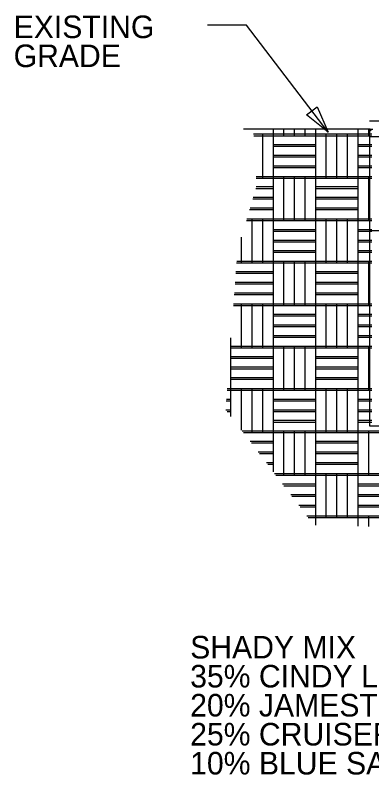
# Model space of a CAD drawing. Extents: x 9915.7 to 9955.7, y 9888.6 to 9936.3.
# Drawn here: x 9915.74 to 9926.81, y 9912.72 to 9936.27 of the extents above; entities that cross this region are included whole.
import ezdxf

# ---------------------------------------------------------------- set-up
doc = ezdxf.new("R2010")
doc.units = 0
for name, color, linetype in [('Default', 7, 'Continuous'), ('G-ANNO-TEXT', 7, 'Continuous'), ('G-ANNO-TTXT', 7, 'Continuous'), ('G-DETL-LINE', 7, 'Continuous'), ('G-DETL-PATT', 7, 'Continuous'), ('L-PLNT-SEED', 7, 'Continuous')]:
    doc.layers.add(name, color=color, linetype=linetype)

# ---------------------------------------------------------------- blocks, each defined once
blk = doc.blocks.new('TERARR')
at = {"layer": 'Default'}
blk.add_lwpolyline([(-0.667, 0.167), (0, 0), (-0.667, -0.167)], close=True, dxfattribs=at)

msp = doc.modelspace()

# ---------------------------------------------------------------- linework, layer by layer
at = {"layer": 'Default'}
for p, q in [((9926.715, 9932.587), (9926.715, 9932.714)), ((9926.715, 9932.534), (9926.715, 9932.714)), ((9926.737, 9932.731), (9926.843, 9932.731)), ((9926.715, 9929.956), (9926.715, 9931.271)), ((9926.715, 9929.903), (9926.715, 9931.219))]:
    msp.add_line(p, q, dxfattribs=at)
at = {"layer": 'G-ANNO-TEXT'}
msp.add_lwpolyline([(9925.458, 9932.644), (9922.921, 9935.959), (9921.709, 9935.959)], dxfattribs=at)
at = {"layer": 'G-ANNO-TTXT'}
msp.add_line((9926.737, 9932.993), (9943.294, 9932.993), dxfattribs=at)
at = {"layer": 'G-DETL-LINE'}
for p, q in [((9926.76, 9932.731), (9922.831, 9932.731)), ((9926.737, 9932.731), (9926.737, 9923.539)), ((9926.737, 9932.508), (9943.291, 9932.508)), ((9926.737, 9929.597), (9943.23, 9929.597)), ((9926.737, 9923.539), (9942.996, 9923.539))]:
    msp.add_line(p, q, dxfattribs=at)
at = {"layer": 'G-DETL-PATT'}
for p, q in [((9923.755, 9932.587), (9923.755, 9932.714)), ((9923.755, 9932.534), (9923.755, 9932.714)), ((9924.084, 9932.587), (9924.084, 9932.714)), ((9924.084, 9932.534), (9924.084, 9932.714)), ((9924.413, 9932.587), (9924.413, 9932.714)), ((9924.413, 9932.534), (9924.413, 9932.714)), ((9924.742, 9932.587), (9924.742, 9932.714)), ((9924.742, 9932.534), (9924.742, 9932.714)), ((9925.071, 9932.587), (9925.071, 9932.714)), ((9925.071, 9932.534), (9925.071, 9932.714)), ((9926.386, 9932.587), (9926.386, 9932.714)), ((9926.386, 9932.534), (9926.386, 9932.714)), ((9923.143, 9932.587), (9926.813, 9932.587)), ((9923.153, 9932.534), (9926.813, 9932.534)), ((9923.426, 9931.271), (9923.426, 9932.587)), ((9923.426, 9931.219), (9923.426, 9932.534)), ((9923.755, 9931.271), (9923.755, 9932.587)), ((9923.755, 9932.587), (9925.071, 9932.587)), ((9923.755, 9931.219), (9923.755, 9932.534)), ((9923.755, 9932.534), (9925.071, 9932.534)), ((9925.071, 9931.271), (9925.071, 9932.587)), ((9925.071, 9931.219), (9925.071, 9932.534)), ((9925.399, 9931.271), (9925.399, 9932.587)), ((9925.399, 9931.219), (9925.399, 9932.534)), ((9925.728, 9931.271), (9925.728, 9932.587)), ((9925.728, 9931.219), (9925.728, 9932.534)), ((9926.057, 9931.271), (9926.057, 9932.587)), ((9926.057, 9931.219), (9926.057, 9932.534)), ((9926.386, 9931.271), (9926.386, 9932.587)), ((9926.386, 9932.587), (9926.813, 9932.587)), ((9926.386, 9931.219), (9926.386, 9932.534)), ((9926.386, 9932.534), (9926.813, 9932.534)), ((9923.755, 9932.258), (9925.071, 9932.258)), ((9926.386, 9932.258), (9926.813, 9932.258)), ((9923.755, 9932.205), (9925.071, 9932.205)), ((9926.386, 9932.205), (9926.813, 9932.205)), ((9923.755, 9931.929), (9925.071, 9931.929)), ((9923.755, 9931.876), (9925.071, 9931.876)), ((9926.386, 9931.929), (9926.813, 9931.929)), ((9926.386, 9931.876), (9926.813, 9931.876)), ((9923.755, 9931.6), (9925.071, 9931.6)), ((9923.755, 9931.548), (9925.071, 9931.548)), ((9926.386, 9931.6), (9926.813, 9931.6)), ((9926.386, 9931.548), (9926.813, 9931.548)), ((9923.223, 9931.271), (9926.813, 9931.271)), ((9923.755, 9929.956), (9923.755, 9931.271)), ((9924.084, 9929.956), (9924.084, 9931.271)), ((9924.413, 9929.956), (9924.413, 9931.271)), ((9924.742, 9929.956), (9924.742, 9931.271)), ((9925.071, 9929.956), (9925.071, 9931.271)), ((9926.386, 9929.956), (9926.386, 9931.271)), ((9923.223, 9931.219), (9926.813, 9931.219)), ((9923.755, 9929.903), (9923.755, 9931.219)), ((9924.084, 9929.903), (9924.084, 9931.219)), ((9924.413, 9929.903), (9924.413, 9931.219)), ((9924.742, 9929.903), (9924.742, 9931.219)), ((9925.071, 9929.903), (9925.071, 9931.219)), ((9926.386, 9929.903), (9926.386, 9931.219)), ((9923.755, 9930.89), (9923.215, 9930.89)), ((9923.755, 9930.943), (9923.223, 9930.943)), ((9926.386, 9930.943), (9925.071, 9930.943)), ((9926.386, 9930.89), (9925.071, 9930.89)), ((9923.755, 9930.561), (9923.117, 9930.561)), ((9923.755, 9930.614), (9923.133, 9930.614)), ((9926.386, 9930.614), (9925.071, 9930.614)), ((9926.386, 9930.561), (9925.071, 9930.561)), ((9923.755, 9930.232), (9923.019, 9930.232)), ((9923.755, 9930.285), (9923.035, 9930.285)), ((9926.386, 9930.285), (9925.071, 9930.285)), ((9926.386, 9930.232), (9925.071, 9930.232)), ((9922.922, 9929.903), (9926.813, 9929.903)), ((9922.937, 9929.956), (9926.813, 9929.956)), ((9923.097, 9928.641), (9923.097, 9929.956)), ((9923.097, 9928.588), (9923.097, 9929.903)), ((9923.426, 9928.641), (9923.426, 9929.956)), ((9923.426, 9928.588), (9923.426, 9929.903)), ((9923.755, 9928.641), (9923.755, 9929.956)), ((9923.755, 9929.956), (9925.071, 9929.956)), ((9923.755, 9928.588), (9923.755, 9929.903)), ((9923.755, 9929.903), (9925.071, 9929.903)), ((9925.071, 9928.641), (9925.071, 9929.956)), ((9925.071, 9928.588), (9925.071, 9929.903)), ((9925.399, 9928.641), (9925.399, 9929.956)), ((9925.399, 9928.588), (9925.399, 9929.903)), ((9925.728, 9928.641), (9925.728, 9929.956)), ((9925.728, 9928.588), (9925.728, 9929.903)), ((9926.057, 9928.641), (9926.057, 9929.956)), ((9926.057, 9928.588), (9926.057, 9929.903)), ((9926.386, 9928.641), (9926.386, 9929.956)), ((9926.386, 9929.956), (9926.813, 9929.956)), ((9926.386, 9928.588), (9926.386, 9929.903)), ((9926.386, 9929.903), (9926.813, 9929.903)), ((9923.755, 9929.627), (9925.071, 9929.627)), ((9926.386, 9929.627), (9926.813, 9929.627)), ((9922.769, 9928.641), (9922.769, 9929.387)), ((9922.769, 9928.588), (9922.769, 9929.387)), ((9923.755, 9929.574), (9925.071, 9929.574)), ((9926.386, 9929.574), (9926.813, 9929.574)), ((9923.755, 9929.298), (9925.071, 9929.298)), ((9923.755, 9929.245), (9925.071, 9929.245)), ((9926.386, 9929.298), (9926.813, 9929.298)), ((9926.386, 9929.245), (9926.813, 9929.245)), ((9923.755, 9928.969), (9925.071, 9928.969)), ((9923.755, 9928.917), (9925.071, 9928.917)), ((9926.386, 9928.969), (9926.813, 9928.969)), ((9926.386, 9928.917), (9926.813, 9928.917)), ((9922.614, 9928.588), (9926.813, 9928.588)), ((9922.618, 9928.641), (9926.813, 9928.641)), ((9923.755, 9927.325), (9923.755, 9928.641)), ((9923.755, 9927.272), (9923.755, 9928.588)), ((9924.084, 9927.325), (9924.084, 9928.641)), ((9924.084, 9927.272), (9924.084, 9928.588)), ((9924.413, 9927.325), (9924.413, 9928.641)), ((9924.413, 9927.272), (9924.413, 9928.588)), ((9924.742, 9927.325), (9924.742, 9928.641)), ((9924.742, 9927.272), (9924.742, 9928.588)), ((9925.071, 9927.325), (9925.071, 9928.641)), ((9925.071, 9927.272), (9925.071, 9928.588)), ((9926.386, 9927.325), (9926.386, 9928.641)), ((9926.386, 9927.272), (9926.386, 9928.588)), ((9926.715, 9927.325), (9926.715, 9928.641)), ((9926.715, 9927.272), (9926.715, 9928.588)), ((9923.755, 9928.259), (9922.589, 9928.259)), ((9923.755, 9928.312), (9922.593, 9928.312)), ((9926.386, 9928.312), (9925.071, 9928.312)), ((9926.386, 9928.259), (9925.071, 9928.259)), ((9923.755, 9927.983), (9922.569, 9927.983)), ((9926.386, 9927.983), (9925.071, 9927.983)), ((9923.755, 9927.93), (9922.565, 9927.93)), ((9926.386, 9927.93), (9925.071, 9927.93)), ((9923.755, 9927.601), (9922.54, 9927.601)), ((9923.755, 9927.654), (9922.544, 9927.654)), ((9926.386, 9927.654), (9925.071, 9927.654)), ((9926.386, 9927.601), (9925.071, 9927.601)), ((9922.515, 9927.272), (9926.813, 9927.272)), ((9922.519, 9927.325), (9926.813, 9927.325)), ((9922.769, 9926.01), (9922.769, 9927.325)), ((9922.769, 9925.957), (9922.769, 9927.272)), ((9923.097, 9926.01), (9923.097, 9927.325)), ((9923.097, 9925.957), (9923.097, 9927.272)), ((9923.426, 9926.01), (9923.426, 9927.325)), ((9923.426, 9925.957), (9923.426, 9927.272)), ((9923.755, 9926.01), (9923.755, 9927.325)), ((9923.755, 9927.325), (9925.071, 9927.325)), ((9923.755, 9925.957), (9923.755, 9927.272)), ((9923.755, 9927.272), (9925.071, 9927.272)), ((9925.071, 9926.01), (9925.071, 9927.325)), ((9925.071, 9925.957), (9925.071, 9927.272)), ((9925.399, 9926.01), (9925.399, 9927.325)), ((9925.399, 9925.957), (9925.399, 9927.272)), ((9925.728, 9926.01), (9925.728, 9927.325)), ((9925.728, 9925.957), (9925.728, 9927.272)), ((9926.057, 9926.01), (9926.057, 9927.325)), ((9926.057, 9925.957), (9926.057, 9927.272)), ((9926.386, 9926.01), (9926.386, 9927.325)), ((9926.386, 9927.325), (9926.813, 9927.325)), ((9926.386, 9925.957), (9926.386, 9927.272)), ((9926.386, 9927.272), (9926.813, 9927.272)), ((9923.755, 9926.996), (9925.071, 9926.996)), ((9923.755, 9926.943), (9925.071, 9926.943)), ((9926.386, 9926.996), (9926.813, 9926.996)), ((9926.386, 9926.943), (9926.813, 9926.943)), ((9923.755, 9926.667), (9925.071, 9926.667)), ((9923.755, 9926.614), (9925.071, 9926.614)), ((9926.386, 9926.667), (9926.813, 9926.667)), ((9926.386, 9926.614), (9926.813, 9926.614)), ((9923.755, 9926.338), (9925.071, 9926.338)), ((9926.386, 9926.338), (9926.813, 9926.338)), ((9922.44, 9926.01), (9922.44, 9926.268)), ((9922.44, 9925.957), (9922.44, 9926.268)), ((9923.755, 9926.286), (9925.071, 9926.286)), ((9926.386, 9926.286), (9926.813, 9926.286)), ((9922.416, 9925.957), (9926.813, 9925.957)), ((9922.42, 9926.01), (9926.813, 9926.01)), ((9922.44, 9924.694), (9922.44, 9926.01)), ((9922.44, 9924.641), (9922.44, 9925.957)), ((9923.755, 9924.694), (9923.755, 9926.01)), ((9923.755, 9924.641), (9923.755, 9925.957)), ((9924.084, 9924.694), (9924.084, 9926.01)), ((9924.084, 9924.641), (9924.084, 9925.957)), ((9924.413, 9924.694), (9924.413, 9926.01)), ((9924.413, 9924.641), (9924.413, 9925.957)), ((9924.742, 9924.694), (9924.742, 9926.01)), ((9924.742, 9924.641), (9924.742, 9925.957)), ((9925.071, 9924.694), (9925.071, 9926.01)), ((9925.071, 9924.641), (9925.071, 9925.957)), ((9926.386, 9924.694), (9926.386, 9926.01)), ((9926.386, 9924.641), (9926.386, 9925.957)), ((9926.715, 9924.694), (9926.715, 9926.01)), ((9926.715, 9924.641), (9926.715, 9925.957)), ((9923.755, 9925.681), (9922.44, 9925.681)), ((9923.755, 9925.628), (9922.44, 9925.628)), ((9926.386, 9925.681), (9925.071, 9925.681)), ((9926.386, 9925.628), (9925.071, 9925.628)), ((9923.755, 9925.352), (9922.44, 9925.352)), ((9923.755, 9925.299), (9922.44, 9925.299)), ((9926.386, 9925.352), (9925.071, 9925.352)), ((9926.386, 9925.299), (9925.071, 9925.299)), ((9923.755, 9925.023), (9922.44, 9925.023)), ((9923.755, 9924.97), (9922.44, 9924.97)), ((9926.386, 9925.023), (9925.071, 9925.023)), ((9926.386, 9924.97), (9925.071, 9924.97)), ((9922.321, 9924.694), (9926.813, 9924.694)), ((9922.321, 9924.694), (9922.44, 9924.694)), ((9922.44, 9923.831), (9922.44, 9924.694)), ((9922.769, 9923.401), (9922.769, 9924.694)), ((9923.097, 9923.379), (9923.097, 9924.694)), ((9923.426, 9923.379), (9923.426, 9924.694)), ((9923.755, 9923.379), (9923.755, 9924.694)), ((9923.755, 9924.694), (9925.071, 9924.694)), ((9925.071, 9923.379), (9925.071, 9924.694)), ((9925.399, 9923.379), (9925.399, 9924.694)), ((9925.728, 9923.379), (9925.728, 9924.694)), ((9926.057, 9923.379), (9926.057, 9924.694)), ((9926.386, 9923.379), (9926.386, 9924.694)), ((9926.386, 9924.694), (9926.813, 9924.694)), ((9922.317, 9924.641), (9926.813, 9924.641)), ((9922.317, 9924.641), (9922.44, 9924.641)), ((9922.44, 9923.831), (9922.44, 9924.641)), ((9922.769, 9923.401), (9922.769, 9924.641)), ((9923.097, 9923.326), (9923.097, 9924.641)), ((9923.426, 9923.326), (9923.426, 9924.641)), ((9923.755, 9923.326), (9923.755, 9924.641)), ((9923.755, 9924.641), (9925.071, 9924.641)), ((9925.071, 9923.326), (9925.071, 9924.641)), ((9925.399, 9923.326), (9925.399, 9924.641)), ((9925.728, 9923.326), (9925.728, 9924.641)), ((9926.057, 9923.326), (9926.057, 9924.641)), ((9926.386, 9923.326), (9926.386, 9924.641)), ((9926.386, 9924.641), (9926.813, 9924.641)), ((9922.293, 9924.312), (9922.44, 9924.312)), ((9922.297, 9924.365), (9922.44, 9924.365)), ((9923.755, 9924.365), (9925.071, 9924.365)), ((9923.755, 9924.312), (9925.071, 9924.312)), ((9926.386, 9924.365), (9926.813, 9924.365)), ((9926.386, 9924.312), (9926.813, 9924.312)), ((9922.283, 9924.036), (9922.44, 9924.036)), ((9922.323, 9923.984), (9922.44, 9923.984)), ((9923.755, 9924.036), (9925.071, 9924.036)), ((9923.755, 9923.984), (9925.071, 9923.984)), ((9926.386, 9924.036), (9926.813, 9924.036)), ((9926.386, 9923.984), (9926.813, 9923.984)), ((9923.755, 9923.708), (9925.071, 9923.708)), ((9923.755, 9923.655), (9925.071, 9923.655)), ((9926.386, 9923.708), (9926.813, 9923.708)), ((9926.386, 9923.655), (9926.813, 9923.655)), ((9922.786, 9923.379), (9943.064, 9923.379)), ((9922.826, 9923.326), (9943.06, 9923.326)), ((9923.755, 9922.11), (9923.755, 9923.379)), ((9923.755, 9922.11), (9923.755, 9923.326)), ((9924.084, 9922.063), (9924.084, 9923.379)), ((9924.084, 9922.01), (9924.084, 9923.326)), ((9924.413, 9922.063), (9924.413, 9923.379)), ((9924.413, 9922.01), (9924.413, 9923.326)), ((9924.742, 9922.063), (9924.742, 9923.379)), ((9924.742, 9922.01), (9924.742, 9923.326)), ((9925.071, 9922.063), (9925.071, 9923.379)), ((9925.071, 9922.01), (9925.071, 9923.326)), ((9926.386, 9922.063), (9926.386, 9923.379)), ((9926.386, 9922.01), (9926.386, 9923.326)), ((9926.715, 9922.063), (9926.715, 9923.379)), ((9926.715, 9922.01), (9926.715, 9923.326)), ((9923.755, 9923.05), (9923.037, 9923.05)), ((9926.386, 9923.05), (9925.071, 9923.05)), ((9923.755, 9922.997), (9923.077, 9922.997)), ((9926.386, 9922.997), (9925.071, 9922.997)), ((9923.755, 9922.721), (9923.288, 9922.721)), ((9923.755, 9922.668), (9923.328, 9922.668)), ((9926.386, 9922.721), (9925.071, 9922.721)), ((9926.386, 9922.668), (9925.071, 9922.668)), ((9923.755, 9922.392), (9923.539, 9922.392)), ((9923.755, 9922.339), (9923.58, 9922.339)), ((9926.386, 9922.392), (9925.071, 9922.392)), ((9926.386, 9922.339), (9925.071, 9922.339)), ((9923.791, 9922.063), (9942.892, 9922.063)), ((9923.791, 9922.063), (9925.071, 9922.063)), ((9923.831, 9922.01), (9942.882, 9922.01)), ((9923.831, 9922.01), (9925.071, 9922.01)), ((9925.071, 9920.748), (9925.071, 9922.063)), ((9925.071, 9920.695), (9925.071, 9922.01)), ((9925.399, 9920.748), (9925.399, 9922.063)), ((9925.399, 9920.695), (9925.399, 9922.01)), ((9925.728, 9920.748), (9925.728, 9922.063)), ((9925.728, 9920.695), (9925.728, 9922.01)), ((9926.057, 9920.748), (9926.057, 9922.063)), ((9926.057, 9920.695), (9926.057, 9922.01)), ((9926.386, 9920.748), (9926.386, 9922.063)), ((9926.386, 9922.063), (9927.702, 9922.063)), ((9926.386, 9920.695), (9926.386, 9922.01)), ((9926.386, 9922.01), (9927.702, 9922.01)), ((9924.042, 9921.734), (9925.071, 9921.734)), ((9924.082, 9921.681), (9925.071, 9921.681)), ((9926.386, 9921.734), (9927.702, 9921.734)), ((9926.386, 9921.681), (9927.702, 9921.681)), ((9924.293, 9921.405), (9925.071, 9921.405)), ((9926.386, 9921.405), (9927.702, 9921.405)), ((9924.334, 9921.353), (9925.071, 9921.353)), ((9926.386, 9921.353), (9927.702, 9921.353)), ((9924.545, 9921.077), (9925.071, 9921.077)), ((9924.585, 9921.024), (9925.071, 9921.024)), ((9926.386, 9921.077), (9927.702, 9921.077)), ((9926.386, 9921.024), (9927.702, 9921.024)), ((9924.796, 9920.748), (9940.805, 9920.748)), ((9924.836, 9920.695), (9940.321, 9920.695)), ((9925.071, 9920.456), (9925.071, 9920.748)), ((9925.071, 9920.456), (9925.071, 9920.695)), ((9926.386, 9920.425), (9926.386, 9920.748)), ((9926.386, 9920.425), (9926.386, 9920.695)), ((9926.715, 9920.417), (9926.715, 9920.748)), ((9926.715, 9920.417), (9926.715, 9920.695))]:
    msp.add_line(p, q, dxfattribs=at)
at = {"layer": 'L-PLNT-SEED'}
for p, q in [((9926.751, 9932.687), (9926.737, 9932.698)), ((9926.751, 9932.685), (9926.75, 9932.687)), ((9926.751, 9932.731), (9926.751, 9932.687)), ((9926.751, 9932.687), (9926.792, 9932.72)), ((9926.751, 9932.685), (9926.753, 9932.687)), ((9926.751, 9932.687), (9926.751, 9932.685))]:
    msp.add_line(p, q, dxfattribs=at)

# ---------------------------------------------------------------- block references
at = {"layer": 'G-ANNO-TEXT', "xscale": 1.24992, "yscale": 1.2499200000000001, "rotation": -52.57489474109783}
msp.add_blockref('TERARR', (9925.458, 9932.644), dxfattribs=at)

# ---------------------------------------------------------------- texts
at = {"layer": 'G-ANNO-TEXT'}
for s, p in [('EXISTING ', (9915.692, 9935.559)), ('GRADE', (9915.692, 9934.66)), ('SHADY MIX', (9921.173, 9916.324)), ('35% CINDY LOU CREEPING RED FESCUE', (9921.173, 9915.425)), ('20% JAMESTOWN IV CHEWINGS RED FESCUE', (9921.173, 9914.525)), ('25% CRUISER PERENNIAL RYEGRASS', (9921.173, 9913.626)), ('10% BLUE SAPPHIRE KENTUCKY BLUEGRASS', (9921.173, 9912.727))]:
    msp.add_text(s, height=0.7, dxfattribs=at).set_placement(p)

doc.saveas('drawing.dxf')
